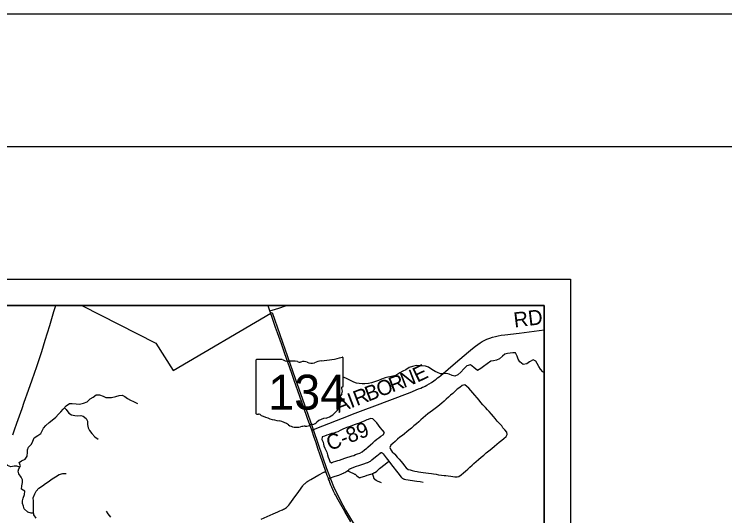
# Model space of a CAD drawing. Extents: x 0 to 34, y 0 to 22.
# Drawn here: x 6.899 to 9.582, y 20.107 to 22 of the extents above; entities that cross this region are included whole.
import ezdxf

# ---------------------------------------------------------------- set-up
doc = ezdxf.new("R2010")
doc.units = 0
for name, color, linetype in [('Default', 7, 'Continuous'), ('GM_X_County_Road', 7, 'Continuous'), ('GM_X_County_Road_Text', 7, 'Continuous'), ('GM_X_Minor_Lake', 7, 'Continuous'), ('GM_X_Minor_River', 7, 'Continuous'), ('GM_X_State_Location', 7, 'Continuous'), ('GM_X_State_Route', 7, 'Continuous'), ('GM_X_State_Shield', 7, 'Continuous'), ('GM_X_Township_Road', 7, 'Continuous'), ('SH_Border', 7, 'Continuous'), ('SH_Cut_Line', 7, 'Continuous'), ('SH_Data', 7, 'Continuous')]:
    doc.layers.add(name, color=color, linetype=linetype)

msp = doc.modelspace()

# ---------------------------------------------------------------- linework, layer by layer
at = {"layer": 'Default'}
msp.add_lwpolyline([(8.9, 20.0527), (8.9, 20.9), (7.1538, 20.9), (7.4333, 20.7587), (7.499, 20.655), (7.8674, 20.8711), (7.8673, 20.8717), (7.8727, 20.8735), (7.9598, 20.6242), (8.0222, 20.4477), (8.0305, 20.4241), (8.0783, 20.2849), (8.1051, 20.2165), (8.13, 20.1655), (8.1505, 20.1279), (8.202, 20.0419)], dxfattribs=at)
at = {"layer": 'GM_X_County_Road'}
for points in [[(6.8935, 20.4116), (6.9004, 20.4316), (6.9088, 20.4562), (6.9187, 20.4837), (6.9285, 20.5119), (6.9368, 20.5359), (6.9526, 20.5804), (6.9666, 20.6203), (6.9844, 20.6707), (6.9944, 20.7001), (7.0031, 20.7273), (7.016, 20.7695), (7.033, 20.8253), (7.0488, 20.8777), (7.0555, 20.9)], [(7.8644, 20.8801), (7.8736, 20.883), (7.8977, 20.8908), (7.9267, 20.9)], [(8.0224, 20.4303), (8.0648, 20.4465), (8.1389, 20.4754), (8.1871, 20.494), (8.2271, 20.5093), (8.2507, 20.518), (8.3938, 20.5725), (8.4261, 20.5854), (8.434, 20.5887), (8.441, 20.5917), (8.4459, 20.5939), (8.4511, 20.5963), (8.4577, 20.5997), (8.4663, 20.6046), (8.4752, 20.6101), (8.4839, 20.6161), (8.4885, 20.6196), (8.4928, 20.6228), (8.498, 20.627), (8.5034, 20.6314), (8.5097, 20.6367), (8.5649, 20.6837), (8.6141, 20.7256), (8.6299, 20.7386), (8.6408, 20.747), (8.6501, 20.7537), (8.6592, 20.7598), (8.6663, 20.7644), (8.6736, 20.7682), (8.6839, 20.7727), (8.6945, 20.7767), (8.7052, 20.7803), (8.716, 20.7834), (8.7269, 20.786), (8.738, 20.7881), (8.7516, 20.7901), (8.8053, 20.7964), (8.8621, 20.8033), (8.9, 20.808)]]:
    msp.add_lwpolyline(points, dxfattribs=at)
at = {"layer": 'GM_X_Minor_Lake'}
for points in [[(8.7092, 20.4814), (8.7089, 20.4817), (8.7018, 20.4902), (8.6932, 20.4998), (8.6861, 20.5067), (8.6786, 20.5155), (8.6688, 20.5255), (8.6617, 20.5343), (8.655, 20.5432), (8.6475, 20.552), (8.6389, 20.5616), (8.6314, 20.5712), (8.6232, 20.58), (8.6157, 20.588), (8.6078, 20.595), (8.6002, 20.6008), (8.59, 20.5978), (8.5812, 20.5911), (8.5723, 20.584), (8.5631, 20.5757), (8.5551, 20.5686), (8.547, 20.5619), (8.5386, 20.5547), (8.5305, 20.5465), (8.5221, 20.539), (8.514, 20.5322), (8.5067, 20.5255), (8.4983, 20.5195), (8.4883, 20.5109), (8.4788, 20.5038), (8.4696, 20.4974), (8.4615, 20.491), (8.4523, 20.4836), (8.4435, 20.4761), (8.4347, 20.4682), (8.427, 20.4614), (8.4182, 20.4532), (8.4082, 20.4465), (8.3994, 20.4378), (8.3891, 20.4296), (8.3818, 20.4236), (8.3729, 20.4157), (8.3653, 20.4101), (8.3557, 20.4034)], [(8.3361, 20.3385), (8.3446, 20.3279), (8.3525, 20.3202), (8.3592, 20.3122), (8.3659, 20.3033), (8.3727, 20.2953), (8.3786, 20.2872), (8.3862, 20.2811), (8.3937, 20.2795), (8.402, 20.2771), (8.4119, 20.2747), (8.4206, 20.2731), (8.4263, 20.2723), (8.4346, 20.271), (8.4437, 20.2698), (8.4539, 20.2685), (8.4634, 20.2673), (8.4744, 20.2656), (8.4827, 20.2644), (8.4926, 20.2631), (8.5017, 20.2608), (8.5127, 20.2595), (8.5229, 20.2586), (8.5286, 20.2585), (8.5373, 20.2573), (8.5472, 20.2557), (8.5551, 20.2548), (8.5635, 20.2532), (8.5722, 20.2531), (8.5779, 20.2549), (8.5867, 20.2605), (8.5955, 20.2692), (8.6036, 20.2748), (8.612, 20.2827), (8.6201, 20.2898), (8.6285, 20.298), (8.6347, 20.3033), (8.6431, 20.3116), (8.6519, 20.3191), (8.6619, 20.3273), (8.6723, 20.3355), (8.6811, 20.3438), (8.6918, 20.3513), (8.7022, 20.361), (8.7121, 20.3696), (8.7217, 20.3768), (8.7305, 20.3842), (8.7401, 20.3925), (8.7485, 20.3985), (8.7566, 20.4056), (8.7601, 20.4132), (8.7587, 20.4223), (8.7516, 20.4307), (8.7448, 20.4384), (8.74, 20.4461), (8.731, 20.4553), (8.7231, 20.4641), (8.7153, 20.4733), (8.7092, 20.4814)], [(8.2814, 20.4395), (8.2814, 20.4396), (8.2679, 20.4572), (8.2608, 20.4652), (8.2537, 20.4729), (8.2438, 20.4738), (8.2358, 20.4701), (8.2301, 20.4683), (8.2202, 20.4642), (8.2102, 20.4594), (8.1996, 20.4553), (8.1935, 20.4531), (8.1866, 20.4509), (8.1767, 20.4468), (8.1679, 20.4439), (8.1592, 20.4406), (8.1485, 20.4369), (8.1405, 20.4332), (8.1298, 20.4284), (8.1206, 20.4239), (8.1119, 20.421), (8.1058, 20.4188), (8.0974, 20.4166), (8.0882, 20.4137), (8.0795, 20.4107), (8.0707, 20.407), (8.0623, 20.4041), (8.0611, 20.3946), (8.0651, 20.385), (8.0673, 20.3763), (8.0687, 20.3706), (8.0724, 20.3614), (8.0743, 20.3572)], [(8.0743, 20.3572), (8.0791, 20.3461), (8.0824, 20.3366), (8.0849, 20.3282), (8.0879, 20.3194), (8.0908, 20.3114), (8.0968, 20.3068), (8.1052, 20.3101), (8.114, 20.3127), (8.1216, 20.3153), (8.1273, 20.3167), (8.138, 20.3204), (8.1479, 20.3245), (8.1586, 20.3281), (8.1643, 20.3296), (8.175, 20.3329), (8.1814, 20.3347), (8.1875, 20.3373), (8.1959, 20.3406), (8.2043, 20.3432), (8.2123, 20.348), (8.2212, 20.3555), (8.2303, 20.3623), (8.2349, 20.366), (8.2438, 20.3743), (8.2526, 20.3818), (8.2603, 20.3889), (8.2683, 20.396), (8.276, 20.4009), (8.284, 20.4069), (8.2921, 20.4125), (8.2971, 20.4204), (8.2892, 20.4292), (8.2814, 20.4395)], [(8.3557, 20.4034), (8.3469, 20.3963), (8.3373, 20.3869), (8.3285, 20.3798), (8.3208, 20.3726), (8.3177, 20.3643), (8.3214, 20.3559), (8.3266, 20.3475), (8.3348, 20.3398), (8.3361, 20.3385)]]:
    msp.add_lwpolyline(points, dxfattribs=at)
at = {"layer": 'GM_X_Minor_River'}
for points in [[(8.9, 20.6478), (8.8954, 20.6498), (8.8864, 20.6605), (8.8797, 20.6701), (8.8734, 20.6812), (8.8693, 20.6907), (8.8587, 20.695), (8.845, 20.6872), (8.8346, 20.6801), (8.8206, 20.678), (8.8078, 20.6877), (8.8018, 20.6972), (8.7989, 20.709), (8.7926, 20.7216), (8.7816, 20.7218), (8.7721, 20.7207), (8.7618, 20.719), (8.7523, 20.7164), (8.7427, 20.7093), (8.732, 20.6995), (8.7206, 20.6944), (8.7084, 20.6911), (8.6989, 20.6908), (8.6851, 20.6799), (8.6713, 20.6698), (8.6617, 20.6631), (8.6483, 20.6549), (8.6352, 20.6668), (8.6216, 20.6769), (8.6087, 20.6725), (8.5975, 20.6608), (8.5853, 20.6492), (8.5745, 20.6383), (8.5627, 20.6339), (8.5528, 20.6363), (8.5415, 20.6417), (8.5309, 20.6441), (8.5199, 20.6423), (8.5093, 20.6421), (8.4979, 20.6471), (8.4881, 20.6507), (8.4761, 20.6592), (8.4629, 20.6681), (8.4527, 20.6712), (8.4398, 20.6729), (8.4299, 20.673), (8.4181, 20.6739), (8.4033, 20.6703), (8.3907, 20.6662), (8.3773, 20.6577), (8.3667, 20.6528), (8.3552, 20.6461), (8.3403, 20.636), (8.3235, 20.6321), (8.3098, 20.6296), (8.2992, 20.627), (8.2862, 20.6222), (8.2744, 20.6174), (8.2629, 20.6134), (8.2481, 20.6082), (8.2367, 20.6053), (8.223, 20.6043), (8.2127, 20.6052), (8.201, 20.6065), (8.1915, 20.6077), (8.1809, 20.6109), (8.1662, 20.6179), (8.156, 20.6237), (8.142, 20.6292)], [(6.9724, 20.1165), (6.963, 20.1158), (6.9501, 20.1205), (6.937, 20.1328), (6.9333, 20.1423), (6.93, 20.1523), (6.9301, 20.1625), (6.9325, 20.1724), (6.9373, 20.1864), (6.9386, 20.1993), (6.9261, 20.2066), (6.9274, 20.2199), (6.9306, 20.232), (6.9296, 20.2427), (6.9255, 20.2526), (6.9166, 20.2645), (6.9133, 20.2744), (6.9157, 20.2842), (6.9222, 20.2948), (6.9171, 20.3074), (6.9266, 20.3137), (6.9396, 20.3204), (6.9477, 20.331), (6.949, 20.3462), (6.9495, 20.3557), (6.9523, 20.3655), (6.9646, 20.3775), (6.9693, 20.3881), (6.9747, 20.4009), (6.9885, 20.4092), (6.9996, 20.417), (7.0047, 20.4272), (7.0093, 20.4374), (7.0186, 20.4479), (7.0305, 20.4581), (7.0416, 20.467), (7.0554, 20.4794), (7.0658, 20.4896), (7.0754, 20.4986), (7.0838, 20.5091), (7.0954, 20.5219), (7.1072, 20.5301), (7.1171, 20.5308), (7.133, 20.5294), (7.1448, 20.5282), (7.1604, 20.5314), (7.1745, 20.5373), (7.1856, 20.5475), (7.1967, 20.5549), (7.2078, 20.5632), (7.2215, 20.5626), (7.2347, 20.5579), (7.2449, 20.5536), (7.2555, 20.5527), (7.2662, 20.553), (7.2822, 20.557), (7.2947, 20.5606), (7.3065, 20.5616), (7.3163, 20.5562), (7.3261, 20.5493), (7.3386, 20.5434), (7.3499, 20.5384), (7.3642, 20.531)], [(7.0888, 20.5146), (7.0952, 20.5078), (7.1045, 20.4933), (7.1155, 20.4871), (7.128, 20.485), (7.139, 20.4842), (7.15, 20.4852), (7.1598, 20.4824), (7.1703, 20.4743), (7.1752, 20.464), (7.1761, 20.4507), (7.1775, 20.4389), (7.1827, 20.4282), (7.1917, 20.4167), (7.2033, 20.4048), (7.2157, 20.3959)], [(6.9194, 20.2902), (6.9089, 20.2942), (6.8983, 20.2939), (6.8858, 20.2914), (6.8729, 20.2965), (6.859, 20.3058), (6.8488, 20.3108), (6.8336, 20.3125), (6.8214, 20.3108), (6.8094, 20.3204), (6.7966, 20.324), (6.7856, 20.3268), (6.775, 20.3276), (6.7651, 20.3285), (6.7549, 20.3302), (6.7442, 20.3307), (6.7333, 20.3315), (6.7215, 20.3313), (6.712, 20.331), (6.7021, 20.3304), (6.6912, 20.3347), (6.6783, 20.3417), (6.6647, 20.3483), (6.6515, 20.3511)], [(6.9814, 20.097), (6.9728, 20.1104), (6.9722, 20.1214), (6.9719, 20.132), (6.9713, 20.1419), (6.9718, 20.1514), (6.9711, 20.1613), (6.9709, 20.1742), (6.9768, 20.1897), (6.9815, 20.1995), (6.9922, 20.2108), (7.0056, 20.2198), (7.0175, 20.2284), (7.0274, 20.2351), (7.0427, 20.2459), (7.0546, 20.2538), (7.0687, 20.262), (7.0821, 20.2656), (7.095, 20.2659)], [(7.2635, 20.1017), (7.2537, 20.114), (7.2478, 20.1239)]]:
    msp.add_lwpolyline(points, dxfattribs=at)
at = {"layer": 'GM_X_State_Route'}
for points in [[(7.8679, 20.8699), (7.8644, 20.8801), (7.8593, 20.8951), (7.8576, 20.9)], [(8.1702, 20.0838), (8.1475, 20.1231), (8.1225, 20.1667), (8.1125, 20.1853), (8.1101, 20.1899), (8.1077, 20.1947), (8.1052, 20.1997), (8.1025, 20.2053), (8.1002, 20.2104), (8.0983, 20.2151), (8.0964, 20.2195), (8.0952, 20.2224), (8.0936, 20.2265), (8.0913, 20.2323), (8.089, 20.2384), (8.0864, 20.245), (8.0857, 20.2469), (8.084, 20.2514), (8.0812, 20.259), (8.0757, 20.2734), (8.0542, 20.3357), (8.0459, 20.36), (8.0386, 20.3815), (8.0318, 20.402), (8.0224, 20.4303), (8.0068, 20.4743), (7.9927, 20.5136), (7.9771, 20.5568), (7.9562, 20.6173), (7.9473, 20.6431), (7.9322, 20.686), (7.921, 20.7182), (7.9079, 20.7552), (7.8934, 20.7968), (7.886, 20.8179), (7.877, 20.8439), (7.8679, 20.8699)]]:
    msp.add_lwpolyline(points, dxfattribs=at)
at = {"layer": 'GM_X_State_Shield'}
for p, q in [((7.8116, 20.6932), (7.8116, 20.4931)), ((7.9114, 20.6966), (7.8149, 20.6966)), ((8.1412, 20.5969), (8.1412, 20.7016)), ((8.1412, 20.5969), (8.1412, 20.5969))]:
    msp.add_line(p, q, dxfattribs=at)
for centre, major_axis, start_param, end_param in [((7.8154, 20.6936), (0.00382, 0), 1.712693, 3.28349), ((7.9344, 20.7199), (0.037, 0), 4.042523, 4.731795), ((8.0684, 20.6355), (0.0703, 0), 1.699011, 2.107814), ((8.0238, 20.9695), (0.3495, 0), 4.814394, 5.042369), ((8.1376, 20.702), (0.00367, 0), 6.141152, 7.989035), ((7.9467, 20.5843), (0.133, 0), 1.404758, 1.657858), ((7.9769, 20.6947), (0.0107, 0), 3.836095, 5.185415), ((7.9925, 20.6715), (0.0222, 0), 0.950623, 2.079405), ((8.0212, 20.7033), (0.0267, 0), 4.081561, 5.145723), ((8.1404, 20.5892), (0.00568, 0), 1.883978, 3.671073), ((8.1043, 20.576), (0.0341, 0), 5.934695, 6.695948), ((8.1373, 20.5965), (0.00393, 0), 5.05454, 6.418171), ((8.1544, 20.5531), (0.0248, 0), 2.387724, 3.262537), ((8.0434, 20.5398), (0.0874, 0), 5.101752, 6.440018), ((7.8155, 20.4926), (0.00385, 0), 3.00124, 4.508301), ((7.816, 20.5131), (0.0294, 0), 4.665946, 4.897461), ((7.8221, 20.4815), (0.0106, 0), 0.519207, 1.627899), ((7.9559, 20.6613), (0.2524, 0), 4.195997, 4.488961), ((7.8806, 20.4032), (0.079, 0), 0.823519, 1.323587), ((7.9987, 20.4656), (0.0267, 0), 4.691044, 5.507374), ((8.0228, 20.4462), (0.00752, 0), 1.147584, 2.315152), ((8.0196, 20.4737), (0.0282, 0), 4.937069, 5.64225), ((8.0803, 20.4369), (0.0479, 0), 1.647645, 2.488434), ((7.966, 20.4805), (0.0501, 0), 4.026481, 4.996735), ((7.995, 20.4114), (0.0412, 0), 1.495662, 1.94098)]:
    msp.add_ellipse(centre, major_axis=major_axis, ratio=0.8, start_param=start_param, end_param=end_param, dxfattribs=at)
at = {"layer": 'GM_X_Township_Road'}
msp.add_lwpolyline([(8.9, 19.1426), (8.9, 20.9), (4.4664, 20.9), (4.4684, 20.7448), (4.4849, 19.6021), (5.1411, 19.5203), (5.6889, 19.4592), (5.8809, 19.4409), (6.3561, 19.3959), (7.1834, 19.2978), (7.8888, 19.2268), (8.4186, 19.1875)], close=True, dxfattribs=at)
for points in [[(8.0857, 20.2469), (8.0901, 20.2485), (8.1106, 20.2556), (8.1246, 20.2604), (8.1363, 20.2648), (8.139, 20.2658), (8.1419, 20.2672), (8.1443, 20.2684), (8.1475, 20.27), (8.1508, 20.272), (8.1548, 20.2744), (8.1562, 20.2754), (8.1577, 20.2766), (8.1624, 20.2804), (8.1643, 20.282), (8.166, 20.2833), (8.1674, 20.2841), (8.1688, 20.2848), (8.1722, 20.2863), (8.1812, 20.2896), (8.1916, 20.2934), (8.1998, 20.2961), (8.2157, 20.3015), (8.2327, 20.3072), (8.2349, 20.3081), (8.2372, 20.3091), (8.2391, 20.31), (8.241, 20.3111), (8.244, 20.3131), (8.2498, 20.3177), (8.2632, 20.3288), (8.2685, 20.3331), (8.2805, 20.3431), (8.2813, 20.3437), (8.2821, 20.3442), (8.2828, 20.3445), (8.2835, 20.3447), (8.2841, 20.3449), (8.2849, 20.3449), (8.2856, 20.3449), (8.2864, 20.3448), (8.287, 20.3446), (8.2877, 20.3444), (8.2886, 20.3439), (8.2895, 20.3432), (8.2907, 20.3422), (8.2918, 20.3409), (8.3035, 20.3255), (8.3131, 20.3128), (8.3241, 20.2984), (8.3481, 20.2682), (8.3603, 20.2526), (8.3627, 20.2499), (8.3638, 20.249), (8.365, 20.248), (8.3663, 20.2472), (8.3675, 20.2464), (8.3685, 20.2459), (8.3697, 20.2454), (8.3712, 20.245), (8.3733, 20.2445), (8.378, 20.2438), (8.4198, 20.2377), (8.432, 20.2358), (8.4429, 20.234)], [(8.1577, 20.2766), (8.1641, 20.2736), (8.1822, 20.2651), (8.1842, 20.2642), (8.186, 20.2632), (8.1872, 20.2625), (8.1885, 20.2616), (8.1903, 20.2604), (8.1918, 20.259), (8.1982, 20.253), (8.1992, 20.252), (8.2003, 20.2514), (8.2012, 20.2509), (8.2022, 20.2505), (8.2036, 20.2503), (8.2051, 20.2505), (8.2068, 20.2509), (8.2093, 20.2518), (8.2235, 20.2563), (8.2324, 20.2593), (8.2455, 20.2634), (8.2507, 20.2652), (8.2523, 20.2659), (8.2554, 20.2671), (8.2576, 20.2681), (8.2588, 20.2687), (8.2599, 20.2694), (8.2617, 20.2705), (8.2636, 20.2718), (8.268, 20.2754), (8.279, 20.2844), (8.2997, 20.3017), (8.3131, 20.3128)], [(7.8315, 20.0935), (7.8762, 20.1136), (7.8939, 20.1213), (7.9019, 20.1247), (7.9086, 20.1277), (7.9121, 20.1293), (7.9153, 20.131), (7.9193, 20.1331), (7.9234, 20.1356), (7.9268, 20.138), (7.93, 20.1406), (7.9323, 20.1429), (7.9356, 20.1466), (7.9396, 20.1514), (7.9587, 20.1775), (7.9706, 20.1942), (7.9829, 20.2113), (7.9889, 20.2193), (7.9907, 20.2217), (7.9928, 20.2241), (7.9952, 20.2267), (7.9971, 20.2286), (7.9996, 20.2309), (8.0018, 20.2326), (8.004, 20.2343), (8.0081, 20.237), (8.0192, 20.2437), (8.0495, 20.2609), (8.0679, 20.2708), (8.0696, 20.2715), (8.071, 20.2721), (8.0729, 20.2727), (8.0757, 20.2734)], [(8.2859, 20.2305), (8.2712, 20.2374), (8.2681, 20.239), (8.2652, 20.2407), (8.2639, 20.2415), (8.2626, 20.2424), (8.2614, 20.2434), (8.2603, 20.2445), (8.2595, 20.2453), (8.2588, 20.2464), (8.2582, 20.2475), (8.2575, 20.2486), (8.2569, 20.2499), (8.2564, 20.2514), (8.2542, 20.2592), (8.2523, 20.2659)]]:
    msp.add_lwpolyline(points, dxfattribs=at)
at = {"layer": 'SH_Border'}
msp.add_lwpolyline([(1.5, 21.5), (33.5, 21.5), (33.5, 0.5), (1.5, 0.5)], close=True, dxfattribs=at)
at = {"layer": 'SH_Cut_Line'}
msp.add_lwpolyline([(0, 0), (34, 0), (34, 22), (0, 22)], close=True, dxfattribs=at)
at = {"layer": 'SH_Data'}
for p, q in [((2, 21), (9, 21)), ((9, 21), (9, 14)), ((2.1, 20.9), (8.9, 20.9)), ((8.9, 20.9), (8.9, 14.1))]:
    msp.add_line(p, q, dxfattribs=at)

# ---------------------------------------------------------------- texts
at = {"layer": 'GM_X_County_Road_Text'}
for s, height, rotation, p in [('RD', 0.05682, 6.8836, (8.7883, 20.8171)), ('E', 0.0568, 25.8843, (8.4214, 20.6084)), ('R', 0.0568, 20.9375, (8.3263, 20.5716)), ('N', 0.0568, 21.0438, (8.3699, 20.5884)), ('O', 0.0568, 20.9403, (8.2796, 20.5538)), ('R', 0.0568, 20.9375, (8.1924, 20.5204)), ('B', 0.0568, 20.9302, (8.236, 20.5371)), ('A', 0.0568, 20.9355, (8.1239, 20.4942)), ('I', 0.0568, 20.939, (8.1706, 20.5121)), ('C-89', 0.05682, 21.1098, (8.0906, 20.3512))]:
    msp.add_text(s, height=height, rotation=rotation, dxfattribs=at).set_placement(p)
at = {"layer": 'GM_X_State_Location'}
msp.add_text('134', height=0.000189, rotation=0, dxfattribs=at).set_placement((7.9059, 20.5661))
for s in ['s', 'r']:
    msp.add_text(s, height=0.000189, dxfattribs=at).set_placement((7.9727, 20.5798))
at = {"layer": 'GM_X_State_Shield'}
msp.add_text('134', height=0.13184, dxfattribs=at).set_placement((7.8582, 20.5072))

doc.saveas('drawing.dxf')
